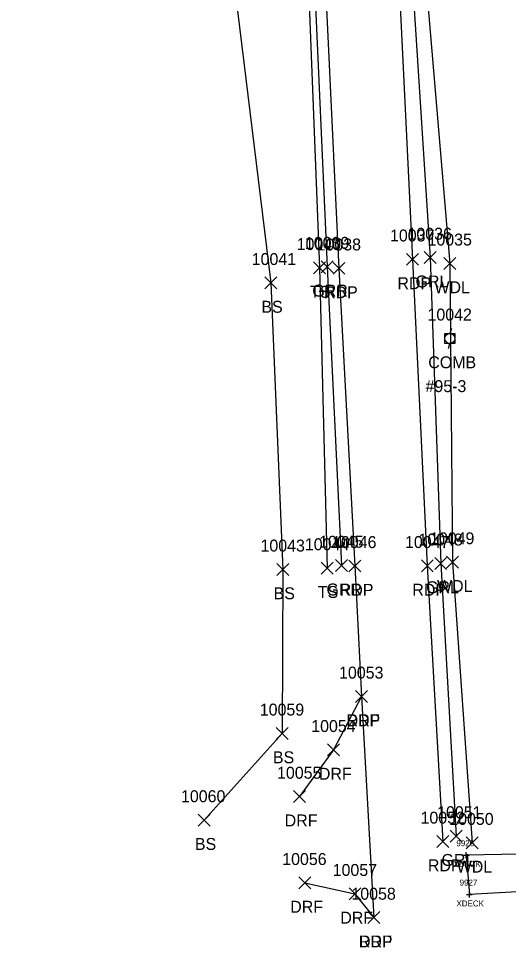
# Model space of a CAD drawing. Extents: x 1769141 to 1770817, y 735471 to 742405.
# Drawn here: x 1770066.7 to 1770148.8, y 740349.2 to 740504.9 of the extents above; entities that cross this region are included whole.
import ezdxf

# ---------------------------------------------------------------- set-up
doc = ezdxf.new("R2010")
doc.units = 0
for name, color, linetype in [('B_A', 7, 'Continuous'), ('B_I', 7, 'Continuous'), ('B_TIC', 7, 'Continuous'), ('BELB', 7, 'Continuous'), ('L_A', 7, 'Continuous'), ('L_I', 7, 'Continuous'), ('L_TIC', 7, 'Continuous'), ('LAWA', 7, 'Continuous'), ('LELB', 7, 'Continuous'), ('P_A', 7, 'Continuous'), ('P_I', 7, 'Continuous'), ('P_TIC', 7, 'Continuous'), ('PET', 7, 'Continuous'), ('R_A', 7, 'Continuous'), ('R_I', 7, 'Continuous'), ('R_TIC', 7, 'Continuous'), ('RDF', 7, 'Continuous'), ('RGR', 7, 'Continuous'), ('U_A', 7, 'Continuous'), ('U_C', 7, 'Continuous'), ('U_I', 7, 'Continuous'), ('UP', 7, 'Continuous')]:
    doc.layers.add(name, color=color, linetype=linetype)

msp = doc.modelspace()

# ---------------------------------------------------------------- linework, layer by layer
at = {"layer": 'B_TIC'}
for p, q in [((1770141.71, 740364.63), (1770141.79, 740364.63)), ((1770142.22, 740358.03), (1770142.3, 740358.03)), ((1770142.22, 740358.03), (1770142.3, 740358.03))]:
    msp.add_line(p, q, dxfattribs=at)
for points in [[(1770141.21, 740364.63), (1770142.21, 740364.63)], [(1770141.71, 740364.13), (1770141.71, 740365.13)], [(1770141.72, 740358.03), (1770142.72, 740358.03)], [(1770141.72, 740358.03), (1770142.72, 740358.03)], [(1770142.22, 740357.53), (1770142.22, 740358.53)], [(1770142.22, 740357.53), (1770142.22, 740358.53)]]:
    msp.add_lwpolyline(points, dxfattribs=at)
at = {"layer": 'BELB'}
for points in [[(1770186.58, 740360.47), (1770186.36, 740365.48), (1770141.71, 740364.63), (1770142.22, 740358.03)], [(1770186.58, 740360.47), (1770142.22, 740358.03)]]:
    msp.add_lwpolyline(points, dxfattribs=at)
at = {"layer": 'L_TIC'}
for points in [[(1770116.12, 740462.09), (1770118.12, 740464.09)], [(1770118.12, 740462.09), (1770116.12, 740464.09)], [(1770137.96, 740462.85), (1770139.96, 740464.85)], [(1770139.96, 740462.85), (1770137.96, 740464.85)], [(1770107.94, 740459.58), (1770109.94, 740461.58)], [(1770109.94, 740459.58), (1770107.94, 740461.58)], [(1770138.39, 740412.76), (1770140.39, 740414.76)], [(1770140.39, 740412.76), (1770138.39, 740414.76)], [(1770109.98, 740411.54), (1770111.98, 740413.54)], [(1770111.98, 740411.54), (1770109.98, 740413.54)], [(1770117.41, 740411.76), (1770119.41, 740413.76)], [(1770119.41, 740411.76), (1770117.41, 740413.76)], [(1770109.87, 740384.04), (1770111.87, 740386.04)], [(1770111.87, 740384.04), (1770109.87, 740386.04)], [(1770096.8, 740369.51), (1770098.8, 740371.51)], [(1770098.8, 740369.51), (1770096.8, 740371.51)], [(1770141.68, 740365.71), (1770143.68, 740367.71)], [(1770143.68, 740365.71), (1770141.68, 740367.71)]]:
    msp.add_lwpolyline(points, dxfattribs=at)
at = {"layer": 'LAWA'}
msp.add_lwpolyline([(1770122.78, 740704.47), (1770125.57, 740659.44), (1770128.91, 740609.51), (1770131.96, 740548.28), (1770134.59, 740515.3), (1770138.96, 740463.85), (1770139.39, 740413.76), (1770142.68, 740366.71)], dxfattribs=at)
at = {"layer": 'LELB'}
for points in [[(1770066.7, 740803.36), (1770072.88, 740768.62), (1770083.55, 740726.83), (1770086.04, 740700.19), (1770091.3, 740659.33), (1770094.84, 740607.83), (1770101.29, 740550.76), (1770100.94, 740526.31), (1770108.94, 740460.58), (1770110.98, 740412.54), (1770110.87, 740385.04), (1770097.8, 740370.51)], [(1770103.5, 740700.99), (1770107.28, 740658.82), (1770110.09, 740608.58), (1770112.97, 740550.02), (1770115.09, 740514.48), (1770117.12, 740463.09), (1770118.41, 740412.76)]]:
    msp.add_lwpolyline(points, dxfattribs=at)
at = {"layer": 'P_TIC'}
for points in [[(1770131.68, 740463.53), (1770133.68, 740465.53)], [(1770133.68, 740463.53), (1770131.68, 740465.53)], [(1770119.38, 740462.02), (1770121.38, 740464.02)], [(1770121.38, 740462.02), (1770119.38, 740464.02)], [(1770122.02, 740412.12), (1770124.02, 740414.12)], [(1770124.02, 740412.12), (1770122.02, 740414.12)], [(1770134.18, 740412.13), (1770136.18, 740414.13)], [(1770136.18, 740412.13), (1770134.18, 740414.13)], [(1770123.14, 740390.24), (1770125.14, 740392.24)], [(1770125.14, 740390.24), (1770123.14, 740392.24)], [(1770136.79, 740365.92), (1770138.79, 740367.92)], [(1770138.79, 740365.92), (1770136.79, 740367.92)], [(1770125.21, 740353.16), (1770127.21, 740355.16)], [(1770127.21, 740353.16), (1770125.21, 740355.16)]]:
    msp.add_lwpolyline(points, dxfattribs=at)
at = {"layer": 'PET'}
for points in [[(1770118.83, 740703.48), (1770122.85, 740659.67), (1770125.57, 740609.37), (1770128.65, 740548.21), (1770130.22, 740515.08), (1770132.68, 740464.53), (1770135.18, 740413.13), (1770137.79, 740366.92)], [(1770106.14, 740701.36), (1770110.18, 740659.08), (1770112.94, 740608.4), (1770116.08, 740549.79), (1770117.88, 740514.91), (1770120.38, 740463.02), (1770123.02, 740413.12), (1770124.14, 740391.24), (1770126.21, 740354.16)]]:
    msp.add_lwpolyline(points, dxfattribs=at)
at = {"layer": 'R_TIC'}
for points in [[(1770134.66, 740463.82), (1770136.66, 740465.82)], [(1770136.66, 740463.82), (1770134.66, 740465.82)], [(1770117.42, 740462.29), (1770119.42, 740464.29)], [(1770119.42, 740462.29), (1770117.42, 740464.29)], [(1770119.8, 740412.18), (1770121.8, 740414.18)], [(1770121.8, 740412.18), (1770119.8, 740414.18)], [(1770136.42, 740412.55), (1770138.42, 740414.55)], [(1770138.42, 740412.55), (1770136.42, 740414.55)], [(1770123.14, 740390.24), (1770125.14, 740392.24)], [(1770125.14, 740390.24), (1770123.14, 740392.24)], [(1770118.48, 740381.28), (1770120.48, 740383.28)], [(1770120.48, 740381.28), (1770118.48, 740383.28)], [(1770112.75, 740373.45), (1770114.75, 740375.45)], [(1770114.75, 740373.45), (1770112.75, 740375.45)], [(1770139, 740366.83), (1770141, 740368.83)], [(1770141, 740366.83), (1770139, 740368.83)], [(1770113.67, 740358.98), (1770115.67, 740360.98)], [(1770115.67, 740358.98), (1770113.67, 740360.98)], [(1770122.06, 740357.15), (1770124.06, 740359.15)], [(1770124.06, 740357.15), (1770122.06, 740359.15)], [(1770125.21, 740353.16), (1770127.21, 740355.16)], [(1770127.21, 740353.16), (1770125.21, 740355.16)]]:
    msp.add_lwpolyline(points, dxfattribs=at)
at = {"layer": 'RDF'}
for points in [[(1770124.14, 740391.24), (1770119.48, 740382.28), (1770113.75, 740374.45)], [(1770114.67, 740359.98), (1770123.06, 740358.15), (1770126.21, 740354.16)]]:
    msp.add_lwpolyline(points, dxfattribs=at)
at = {"layer": 'RGR'}
for points in [[(1770121.12, 740703.83), (1770124.89, 740659.66), (1770127.38, 740609.54), (1770130.69, 740548.36), (1770132.41, 740515.26), (1770135.66, 740464.82), (1770137.42, 740413.55), (1770140, 740367.83)], [(1770104.28, 740701.3), (1770108.06, 740659.13), (1770111.14, 740608.55), (1770114.23, 740549.9), (1770116.09, 740514.54), (1770118.42, 740463.29), (1770120.8, 740413.18)]]:
    msp.add_lwpolyline(points, dxfattribs=at)
at = {"layer": 'UP'}
for p, q in [((1770139.21, 740452.93), (1770138.96, 740452.1)), ((1770138.12, 740450.43), (1770138.12, 740452.1)), ((1770138.12, 740452.1), (1770139.79, 740452.1)), ((1770138.96, 740451.27), (1770138.96, 740451.27)), ((1770139.79, 740452.1), (1770139.79, 740450.43)), ((1770139.79, 740450.43), (1770138.12, 740450.43)), ((1770138.71, 740449.6), (1770138.96, 740450.43))]:
    msp.add_line(p, q, dxfattribs=at)
msp.add_circle((1770138.96, 740451.27), 0.833, dxfattribs=at)

# ---------------------------------------------------------------- texts
at = {"layer": 'B_A'}
for p in [(1770139.55, 740362.63), (1770140.06, 740356.03), (1770140.06, 740356.03)]:
    msp.add_text('XDECK', height=1, dxfattribs=at).set_placement(p)
at = {"layer": 'B_I'}
for s, p in [('9926', (1770140.05, 740366.13)), ('9927', (1770140.59, 740359.53)), ('9927', (1770140.59, 740359.53))]:
    msp.add_text(s, height=1, dxfattribs=at).set_placement(p)
at = {"layer": 'L_A'}
for s, p in [('WDL', (1770136.37, 740458.85)), ('TS', (1770115.53, 740458.09)), ('BS', (1770107.38, 740455.58)), ('WDL', (1770136.8, 740408.76)), ('BS', (1770109.42, 740407.54)), ('TS', (1770116.82, 740407.76)), ('BS', (1770109.31, 740380.04)), ('BS', (1770096.24, 740365.51)), ('WDL', (1770140.1, 740361.71))]:
    msp.add_text(s, height=2, dxfattribs=at).set_placement(p)
at = {"layer": 'L_I'}
for s, p in [('10035', (1770135.21, 740466.85)), ('10040', (1770113.29, 740466.09)), ('10041', (1770105.76, 740463.58)), ('10049', (1770135.63, 740416.76)), ('10043', (1770107.23, 740415.54)), ('10044', (1770114.66, 740415.76)), ('10059', (1770107.11, 740388.04)), ('10060', (1770093.91, 740373.51)), ('10050', (1770138.85, 740369.71))]:
    msp.add_text(s, height=2, dxfattribs=at).set_placement(p)
at = {"layer": 'P_A'}
for p in [(1770130.17, 740459.53), (1770117.87, 740458.02), (1770120.51, 740408.12), (1770132.67, 740408.13), (1770121.63, 740386.24), (1770135.28, 740361.92), (1770123.7, 740349.16)]:
    msp.add_text('RDP', height=2, dxfattribs=at).set_placement(p)
at = {"layer": 'P_I'}
for s, p in [('10037', (1770128.93, 740467.53)), ('10038', (1770116.63, 740466.02)), ('10046', (1770119.22, 740416.12)), ('10047', (1770131.44, 740416.13)), ('10053', (1770120.39, 740394.24)), ('10052', (1770134.04, 740369.92)), ('10058', (1770122.46, 740357.16))]:
    msp.add_text(s, height=2, dxfattribs=at).set_placement(p)
at = {"layer": 'R_A'}
for s, p in [('GRL', (1770133.21, 740459.82)), ('GRR', (1770115.91, 740458.29)), ('GRR', (1770118.28, 740408.18)), ('GRL', (1770134.97, 740408.55)), ('DRF', (1770121.67, 740386.24)), ('DRF', (1770117.01, 740377.28)), ('DRF', (1770111.28, 740369.45)), ('GRL', (1770137.55, 740362.83)), ('DRF', (1770112.21, 740354.98)), ('DRF', (1770120.6, 740353.15)), ('DRF', (1770123.74, 740349.16))]:
    msp.add_text(s, height=2, dxfattribs=at).set_placement(p)
at = {"layer": 'R_I'}
for s, p in [('10036', (1770131.86, 740467.82)), ('10039', (1770114.67, 740466.29)), ('10048', (1770133.68, 740416.55)), ('10045', (1770117.05, 740416.18)), ('10053', (1770120.39, 740394.24)), ('10054', (1770115.73, 740385.28)), ('10055', (1770110, 740377.45)), ('10051', (1770136.82, 740370.83)), ('10056', (1770110.87, 740362.98)), ('10057', (1770119.32, 740361.15)), ('10058', (1770122.46, 740357.16))]:
    msp.add_text(s, height=2, dxfattribs=at).set_placement(p)
at = {"layer": 'U_A'}
msp.add_text('COMB', height=2, dxfattribs=at).set_placement((1770135.34, 740446.27))
at = {"layer": 'U_C'}
msp.add_text('#95-3', height=2, dxfattribs=at).set_placement((1770134.88, 740442.27))
at = {"layer": 'U_I'}
msp.add_text('10042', height=2, dxfattribs=at).set_placement((1770135.21, 740454.27))

doc.saveas('drawing.dxf')
